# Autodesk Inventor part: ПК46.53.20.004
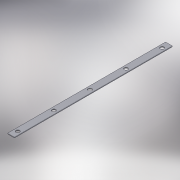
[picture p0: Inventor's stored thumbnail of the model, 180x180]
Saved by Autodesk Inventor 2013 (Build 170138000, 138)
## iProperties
Created: 2005-03
Part Number: ПК46.53.20.004
Material: Steel, Mild
Document SubType Name: Modeling
Designer: HKostja
Manufacturer: Standard
Standards Organization: Custom
Description: Пластина
Density: 7.86 g/cm^3
Mass: 213.034 g
Surface Area: 216.345 cm^2
Volume: 27.1035 cm^3
Author: HKostja
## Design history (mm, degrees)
sketch "Эскиз1"
  geometry: L1 (0, 0)-(-20, 0); L2 (-20, 0)-(-20, 480); L3 (-20, 480)-(0, 480); L4 (0, 480)-(0, 0); L5 (-10, 480)-(-10, 0); C1 r 6 at (-10, 20); C2 r 6 at (-10, 130); C3 r 6 at (-10, 240); C4 r 6 at (-10, 350); C5 r 6 at (-10, 460)
  constraints: 10 end point, 5 centre point, 4 equal radius, 4 point on line, 3 midpoint, 2 parallel, 1 horizontal, 1 perpendicular, 1 other
  dimensions: "d0" = 20 distance of L1.start L1.end; "d1" = 480 distance of L3.end L1.start; "d2" = 110 distance of C2.centre C1.centre; "d3" = 110 distance of C3.centre C2.centre (= d2); "d4" = 110 distance of C5.centre C4.centre (= d2); "d5" = 110 distance of C4.centre C3.centre (= d2); "d6" = 20 distance from line of L1 C1.centre; "d7" = 12 diameter of C1
extrude "Выдавливание1" new body sketch "Эскиз1" distance "d8" = 3; taper "d9" = 0 deg
body "Solid1"
